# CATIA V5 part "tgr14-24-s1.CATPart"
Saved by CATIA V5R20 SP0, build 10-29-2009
Part number: TGR14-24-S1
Revision: 1
Definition: design
Nomenclature: TGR14-24-S1
Source: made
Description: NOT SPECIFIED
Bounding box of the stored display mesh (mm): x -22 to 0.8, y 0 to 14, z -7 to 7
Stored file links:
  C:\Users\Raffaele\Desktop\3D X SITO CF\I-MOLD\TGR-S1\tgr14-s1.step\tgr14-24-s1.CATPart
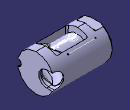
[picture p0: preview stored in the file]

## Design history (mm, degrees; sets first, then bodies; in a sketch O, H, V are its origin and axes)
Set1
  Line1 "LINE #4505": stored without definition
  DatumCurve1 "COMPOSITE_CURVE #4558"
  DatumCurve2 "COMPOSITE_CURVE #4609"
  DatumCurve3 "COMPOSITE_CURVE #4688"
  DatumCurve4 "COMPOSITE_CURVE #4731"
  DatumCurve5 "COMPOSITE_CURVE #4960"
  DatumCurve6 "COMPOSITE_CURVE #5101"
  DatumCurve7 "COMPOSITE_CURVE #5128"
  DatumCurve8 "COMPOSITE_CURVE #5186"
  DatumCurve9 "COMPOSITE_CURVE #5241"
  DatumCurve10 "COMPOSITE_CURVE #5270"
  DatumSurface1 "OPEN_SHELL #4495"
Body1 "MANIFOLD_SOLID_BREP #4496" (main body)
  Solid1: solid without history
